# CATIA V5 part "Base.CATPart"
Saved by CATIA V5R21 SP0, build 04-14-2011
Part number: Part1
Bounding box of the stored display mesh (mm): x -50 to 50, y -25 to 25, z 0 to 50
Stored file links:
  D:\CATIA V5R21 E-RESOURCES\CATIA-V5R21\catia-v5r21-Prts\c12-catia-v5r21-prt\c12_catia_v5r21figr_12-15\Base_cat_v5r21.CATPart
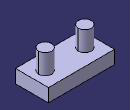
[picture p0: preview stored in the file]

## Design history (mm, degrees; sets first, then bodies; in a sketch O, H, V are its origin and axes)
Body1 (main body)
  Sketch1 on xy-plane, origin (0, 0, 0), H (1, 0, 0), V (0, 1, 0)
    line L1 (50, 25) -> (50, -25)
    line L2 (50, -25) -> (-50, -25)
    line L3 (-50, -25) -> (-50, 25)
    line L4 (-50, 25) -> (50, 25)
    circle A1 centre (-30, 0) radius 10
    point P5 (-30, 0)
    circle A2 centre (30, 0) radius 10
    length L2 = 100
    length L1 = 50
    radius A1 = 10
    distance P5 V = 30
    vertical: L1 V, L3 V
    horizontal: L2 H, L4 H
    equidistance: L1 L3 O, L2 L4 O
    coincidence: P5 H
    symmetry: A1 A2 V
  MultiPad1: profile Sketch1, domains (length 20; length 50; length 50)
